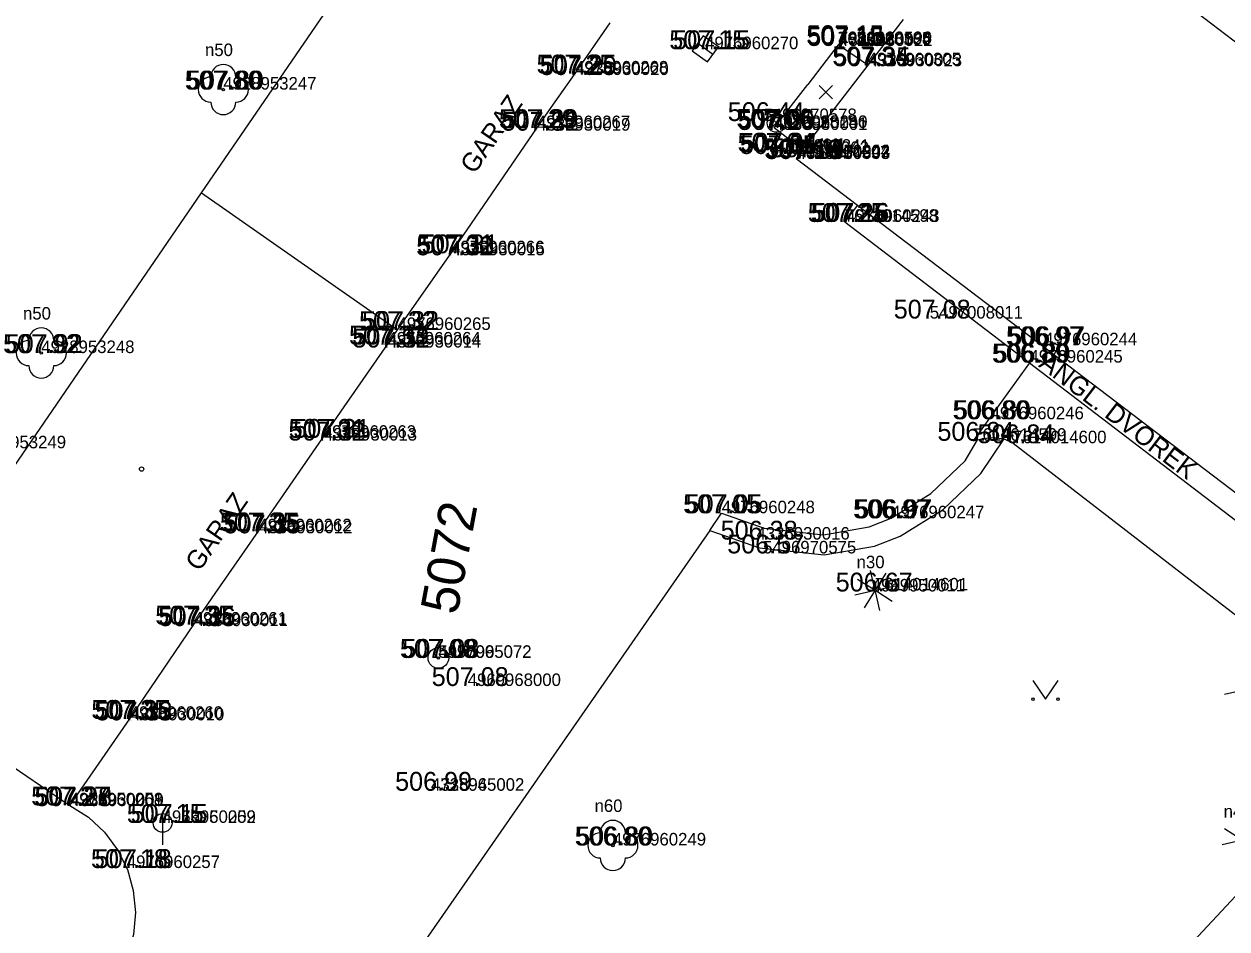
# Model space of a CAD drawing. Extents: x -669251 to -668549, y -1128351 to -1127698.
# Drawn here: x -668695.76 to -668647.77, y -1128038.19 to -1128002.1 of the extents above; entities that cross this region are included whole.
import ezdxf

# ---------------------------------------------------------------- set-up
doc = ezdxf.new("R2010")
doc.units = 0
for name, color, linetype in [('Vrstva 1', 7, 'Continuous'), ('Vrstva 10', 7, 'Continuous'), ('Vrstva 11', 7, 'Continuous'), ('Vrstva 2', 7, 'Continuous'), ('Vrstva 22', 7, 'Continuous'), ('Vrstva 27', 7, 'Continuous'), ('Vrstva 3', 7, 'Continuous'), ('Vrstva 33', 7, 'Continuous'), ('Vrstva 36', 7, 'Continuous'), ('Vrstva 41', 7, 'Continuous'), ('Vrstva 42', 7, 'Continuous'), ('Vrstva 47', 7, 'Continuous'), ('Vrstva 5', 7, 'Continuous'), ('Vrstva 58', 7, 'Continuous'), ('Vrstva 6', 7, 'Continuous'), ('Vrstva 63', 7, 'Continuous')]:
    doc.layers.add(name, color=color, linetype=linetype)

msp = doc.modelspace()

# ---------------------------------------------------------------- linework, layer by layer
at = {"layer": 'Vrstva 1'}
for p, q in [((-668663.29, -1128002.92), (-668663.29, -1128002.92)), ((-668663.29, -1128002.92), (-668663.29, -1128002.92)), ((-668663.28, -1128002.92), (-668663.28, -1128002.92)), ((-668663.259, -1128002.896), (-668663.259, -1128002.896)), ((-668663.24, -1128002.97), (-668663.24, -1128002.97)), ((-668668.59, -1128003.1), (-668668.59, -1128003.1)), ((-668662.1, -1128003.74), (-668662.1, -1128003.74)), ((-668662.06, -1128003.78), (-668662.06, -1128003.78)), ((-668673.78, -1128004.07), (-668673.78, -1128004.07)), ((-668673.76, -1128004.13), (-668673.76, -1128004.13)), ((-668687.81, -1128004.71), (-668687.81, -1128004.71)), ((-668675.3, -1128006.25), (-668675.3, -1128006.25)), ((-668675.29, -1128006.35), (-668675.29, -1128006.35)), ((-668666.258, -1128005.966), (-668666.258, -1128005.966)), ((-668665.85, -1128006.24), (-668665.85, -1128006.24)), ((-668665.85, -1128006.24), (-668665.85, -1128006.24)), ((-668665.83, -1128006.24), (-668665.83, -1128006.24)), ((-668665.83, -1128006.32), (-668665.83, -1128006.32)), ((-668665.77, -1128007.28), (-668665.77, -1128007.28)), ((-668665.74, -1128007.19), (-668665.74, -1128007.19)), ((-668664.954, -1128007.464), (-668664.954, -1128007.464)), ((-668664.93, -1128007.41), (-668664.93, -1128007.41)), ((-668664.93, -1128007.41), (-668664.93, -1128007.41)), ((-668664.93, -1128007.48), (-668664.93, -1128007.48)), ((-668663.016, -1128009.985), (-668663.016, -1128009.985)), ((-668662.96, -1128009.99), (-668662.96, -1128009.99)), ((-668678.72, -1128011.24), (-668678.72, -1128011.24)), ((-668678.7, -1128011.32), (-668678.7, -1128011.32)), ((-668659.629, -1128013.844), (-668659.629, -1128013.844)), ((-668680.86, -1128014.3), (-668680.86, -1128014.3)), ((-668681.26, -1128014.88), (-668681.26, -1128014.88)), ((-668681.24, -1128015), (-668681.24, -1128015)), ((-668655.07, -1128014.91), (-668655.07, -1128014.91)), ((-668695.07, -1128015.22), (-668695.07, -1128015.22)), ((-668655.65, -1128015.6), (-668655.65, -1128015.6)), ((-668657.2, -1128017.86), (-668657.2, -1128017.86)), ((-668683.84, -1128018.6), (-668683.84, -1128018.6)), ((-668683.8, -1128018.71), (-668683.8, -1128018.71)), ((-668657.894, -1128018.719), (-668657.894, -1128018.719)), ((-668656.296, -1128018.817), (-668656.296, -1128018.817)), ((-668667.93, -1128021.61), (-668667.93, -1128021.61)), ((-668661.17, -1128021.81), (-668661.17, -1128021.81)), ((-668686.41, -1128022.33), (-668686.41, -1128022.33)), ((-668686.38, -1128022.41), (-668686.38, -1128022.41)), ((-668666.54, -1128022.66), (-668666.54, -1128022.66)), ((-668666.279, -1128023.212), (-668666.279, -1128023.212)), ((-668661.94, -1128024.73), (-668661.94, -1128024.73)), ((-668661.817, -1128024.689), (-668661.817, -1128024.689)), ((-668688.99, -1128026.05), (-668688.99, -1128026.05)), ((-668688.95, -1128026.11), (-668688.95, -1128026.11)), ((-668679.232, -1128027.376), (-668679.232, -1128027.376)), ((-668679.23, -1128027.38), (-668679.23, -1128027.38)), ((-668679.23, -1128027.38), (-668679.23, -1128027.38)), ((-668678.06, -1128028.5), (-668678.06, -1128028.5)), ((-668691.54, -1128029.81), (-668691.54, -1128029.81)), ((-668691.49, -1128029.87), (-668691.49, -1128029.87)), ((-668679.521, -1128032.677), (-668679.521, -1128032.677)), ((-668679.52, -1128032.68), (-668679.52, -1128032.68)), ((-668693.93, -1128033.26), (-668693.93, -1128033.26)), ((-668693.93, -1128033.26), (-668693.93, -1128033.26)), ((-668693.9, -1128033.29), (-668693.9, -1128033.29)), ((-668690.23, -1128033.96), (-668690.23, -1128033.96)), ((-668690.23, -1128033.96), (-668690.23, -1128033.96)), ((-668672.27, -1128034.86), (-668672.27, -1128034.86)), ((-668691.66, -1128035.76), (-668691.66, -1128035.76))]:
    msp.add_line(p, q, dxfattribs=at)
at = {"layer": 'Vrstva 10'}
for p, q in [((-668655.655, -1128015.606), (-668657.894, -1128018.719)), ((-668658.216, -1128019.518), (-668657.726, -1128018.677)), ((-668657.587, -1128020.023), (-668656.658, -1128018.643)), ((-668659.582, -1128020.827), (-668658.216, -1128019.518)), ((-668659.088, -1128021.462), (-668657.587, -1128020.023)), ((-668661.17, -1128021.81), (-668659.582, -1128020.827)), ((-668668.403, -1128022.291), (-668667.93, -1128021.61)), ((-668667.93, -1128021.61), (-668666.24, -1128022.207)), ((-668660.808, -1128022.527), (-668659.088, -1128021.462)), ((-668666.24, -1128022.207), (-668663.87, -1128022.465)), ((-668663.87, -1128022.465), (-668662.041, -1128022.15)), ((-668662.041, -1128022.15), (-668661.17, -1128021.81)), ((-668668.403, -1128022.291), (-668686.448, -1128048.279)), ((-668668.403, -1128022.291), (-668666.419, -1128022.991)), ((-668661.83, -1128022.925), (-668660.808, -1128022.527)), ((-668666.419, -1128022.991), (-668663.84, -1128023.272)), ((-668663.84, -1128023.272), (-668661.83, -1128022.925))]:
    msp.add_line(p, q, dxfattribs=at)
for points in [[(-668657.894, -1128018.719), (-668657.726, -1128018.677)], [(-668657.726, -1128018.677), (-668657.36, -1128018.609), (-668657.074, -1128018.591), (-668656.658, -1128018.643)], [(-668656.658, -1128018.643), (-668656.296, -1128018.817), (-668648.83, -1128024.582), (-668641.364, -1128030.347)], [(-668693.93, -1128033.26), (-668693.19, -1128033.731), (-668692.548, -1128034.328), (-668692.024, -1128035.031), (-668691.637, -1128035.818), (-668691.399, -1128036.662), (-668691.318, -1128037.535), (-668691.397, -1128038.409), (-668691.632, -1128039.253), (-668691.78, -1128039.6)]]:
    msp.add_lwpolyline(points, dxfattribs=at)
at = {"layer": 'Vrstva 11'}
for p, q in [((-668662.511, -1128009.321), (-668663.016, -1128009.985)), ((-668663.016, -1128009.985), (-668655.655, -1128015.606)), ((-668655.655, -1128015.606), (-668641.204, -1128026.641))]:
    msp.add_line(p, q, dxfattribs=at)
at = {"layer": 'Vrstva 22'}
for p, q in [((-668661.825, -1128024.649), (-668661.997, -1128023.895)), ((-668661.383, -1128023.999), (-668661.797, -1128024.655)), ((-668661.851, -1128024.669), (-668662.507, -1128024.255)), ((-668661.777, -1128024.681), (-668661.023, -1128024.509)), ((-668662.611, -1128024.869), (-668661.857, -1128024.697)), ((-668661.837, -1128024.723), (-668662.251, -1128025.379)), ((-668661.809, -1128024.729), (-668661.637, -1128025.483)), ((-668661.127, -1128025.123), (-668661.783, -1128024.709)), ((-668647.869, -1128028.828), (-668647.115, -1128028.656)), ((-668647.21, -1128034.616), (-668647.866, -1128034.202)), ((-668647.97, -1128034.816), (-668647.216, -1128034.644))]:
    msp.add_line(p, q, dxfattribs=at)
for centre, radius in [((-668687.81, -1128004.71), 0.05), ((-668695.07, -1128015.22), 0.05), ((-668661.817, -1128024.689), 0.04), ((-668672.27, -1128034.86), 0.05)]:
    msp.add_circle(centre, radius, dxfattribs=at)
for centre, start, end in [((-668687.81, -1128004.21), 0, 180), ((-668688.31, -1128004.71), 90, 270), ((-668687.31, -1128004.71), 270, 90), ((-668687.81, -1128005.21), 180, 0), ((-668695.07, -1128014.72), 0, 180), ((-668695.57, -1128015.22), 90, 270), ((-668694.57, -1128015.22), 270, 90), ((-668695.07, -1128015.72), 180, 0), ((-668672.27, -1128034.36), 0, 180), ((-668672.77, -1128034.86), 90, 270), ((-668671.77, -1128034.86), 270, 90), ((-668672.27, -1128035.36), 180, 0)]:
    msp.add_arc(centre, 0.5, start, end, dxfattribs=at)
at = {"layer": 'Vrstva 27'}
for p, q in [((-668668.884, -1128002.866), (-668668.277, -1128003.305)), ((-668690.23, -1128033.585), (-668690.23, -1128034.835))]:
    msp.add_line(p, q, dxfattribs=at)
msp.add_lwpolyline([(-668669.104, -1128003.168), (-668668.496, -1128003.608), (-668668.056, -1128003.001), (-668668.664, -1128002.561)], close=True, dxfattribs=at)
msp.add_circle((-668690.23, -1128033.96), 0.375, dxfattribs=at)
at = {"layer": 'Vrstva 33'}
for p, q in [((-668666.005, -1128005.775), (-668665.475, -1128006.305)), ((-668666.005, -1128006.305), (-668665.475, -1128005.775)), ((-668665.74, -1128007.19), (-668665.74, -1128006.415))]:
    msp.add_line(p, q, dxfattribs=at)
for centre, radius in [((-668665.74, -1128006.04), 0.375), ((-668665.74, -1128007.19), 0.19), ((-668665.74, -1128007.19), 0.05)]:
    msp.add_circle(centre, radius, dxfattribs=at)
at = {"layer": 'Vrstva 36'}
for p, q in [((-668655.512, -1128028.277), (-668655.012, -1128029.027)), ((-668655.012, -1128029.027), (-668654.512, -1128028.277))]:
    msp.add_line(p, q, dxfattribs=at)
for centre in [(-668655.513, -1128029.027), (-668654.513, -1128029.027)]:
    msp.add_circle(centre, 0.05, dxfattribs=at)
at = {"layer": 'Vrstva 5'}
for p, q in [((-668688.674, -1128008.827), (-668680.57, -1127997.01)), ((-668631.975, -1128014.617), (-668653.726, -1127998.018)), ((-668660.694, -1128001.913), (-668662.1, -1128003.74)), ((-668663.28, -1128002.92), (-668663.767, -1128003.554)), ((-668662.1, -1128003.74), (-668663.28, -1128002.92)), ((-668662.1, -1128003.74), (-668664.7, -1128007.112)), ((-668674.728, -1128005.429), (-668673.78, -1128004.07)), ((-668665.83, -1128006.24), (-668664.498, -1128004.506)), ((-668678.72, -1128011.24), (-668675.3, -1128006.25)), ((-668664.7, -1128007.112), (-668665.83, -1128006.24)), ((-668664.7, -1128007.112), (-668664.954, -1128007.464)), ((-668664.954, -1128007.464), (-668662.511, -1128009.321)), ((-668700.28, -1128025.75), (-668688.674, -1128008.827)), ((-668688.674, -1128008.827), (-668680.86, -1128014.3)), ((-668662.511, -1128009.321), (-668640.662, -1128025.932)), ((-668680.86, -1128014.3), (-668680.458, -1128013.726)), ((-668681.26, -1128014.88), (-668680.86, -1128014.3)), ((-668683.84, -1128018.6), (-668682.985, -1128017.367)), ((-668686.41, -1128022.33), (-668685.558, -1128021.094)), ((-668688.99, -1128026.05), (-668688.135, -1128024.817)), ((-668701.766, -1128027.939), (-668693.93, -1128033.26)), ((-668691.54, -1128029.81), (-668690.698, -1128028.568)), ((-668652.247, -1128042.052), (-668641.364, -1128030.347)), ((-668693.93, -1128033.26), (-668693.246, -1128032.273))]:
    msp.add_line(p, q, dxfattribs=at)
at = {"layer": 'Vrstva 58'}
for p, q in [((-668663.511, -1128005.074), (-668664.042, -1128004.544)), ((-668664.042, -1128005.074), (-668663.511, -1128004.544))]:
    msp.add_line(p, q, dxfattribs=at)
msp.add_circle((-668691.067, -1128019.847), 0.0875, dxfattribs=at)
at = {"layer": 'Vrstva 6'}
for p, q in [((-668673.78, -1128004.07), (-668672.38, -1128002.05)), ((-668663.767, -1128003.554), (-668664.498, -1128004.506)), ((-668675.3, -1128006.25), (-668674.728, -1128005.429)), ((-668680.458, -1128013.726), (-668678.72, -1128011.24)), ((-668682.985, -1128017.367), (-668681.26, -1128014.88)), ((-668685.558, -1128021.094), (-668683.84, -1128018.6)), ((-668688.135, -1128024.817), (-668686.41, -1128022.33)), ((-668690.698, -1128028.568), (-668688.99, -1128026.05)), ((-668693.246, -1128032.273), (-668691.54, -1128029.81))]:
    msp.add_line(p, q, dxfattribs=at)
at = {"layer": 'Vrstva 63'}
for radius in [0.412, 0.412, 0.05, 0.05]:
    msp.add_circle((-668679.23, -1128027.38), radius, dxfattribs=at)

# ---------------------------------------------------------------- texts
at = {"layer": 'Vrstva 2'}
for s, p in [('4976960304', (-668663.28, -1128002.92)), ('7682018185', (-668663.29, -1128002.92)), ('7682028185', (-668663.29, -1128002.92)), ('7960020596', (-668663.259, -1128002.896)), ('4335930022', (-668663.24, -1128002.97)), ('4976960270', (-668668.59, -1128003.1)), ('4976960305', (-668662.1, -1128003.74)), ('4335930023', (-668662.06, -1128003.78)), ('4976960268', (-668673.78, -1128004.07)), ('4335930020', (-668673.76, -1128004.13)), ('4928953247', (-668687.81, -1128004.71)), ('4976960267', (-668675.3, -1128006.25)), ('4335930019', (-668675.29, -1128006.35)), ('5496970578', (-668666.258, -1128005.966)), ('7682018186', (-668665.85, -1128006.24)), ('7682028186', (-668665.85, -1128006.24)), ('4976960240', (-668665.83, -1128006.24)), ('4335930001', (-668665.83, -1128006.32)), ('4335930002', (-668665.77, -1128007.28)), ('4976960241', (-668665.74, -1128007.19)), ('7614014597', (-668664.954, -1128007.464)), ('4969950004', (-668664.93, -1128007.41)), ('4976960242', (-668664.93, -1128007.41)), ('4335930003', (-668664.93, -1128007.48)), ('7614014598', (-668663.016, -1128009.985)), ('4976960243', (-668662.96, -1128009.99)), ('4976960266', (-668678.72, -1128011.24)), ('4335930015', (-668678.7, -1128011.32)), ('5497008011', (-668659.629, -1128013.844)), ('4976960265', (-668680.86, -1128014.3)), ('4976960264', (-668681.26, -1128014.88)), ('4335930014', (-668681.24, -1128015)), ('4976960244', (-668655.07, -1128014.91)), ('4928953248', (-668695.07, -1128015.22)), ('4976960245', (-668655.65, -1128015.6)), ('4976960246', (-668657.2, -1128017.86)), ('4976960263', (-668683.84, -1128018.6)), ('4335930013', (-668683.8, -1128018.71)), ('7614014599', (-668657.894, -1128018.719)), ('7614014600', (-668656.296, -1128018.817)), ('4928953249', (-668697.8, -1128019.02)), ('4976960248', (-668667.93, -1128021.61)), ('4976960247', (-668661.17, -1128021.81)), ('4976960262', (-668686.41, -1128022.33)), ('4335930012', (-668686.38, -1128022.41)), ('4335930016', (-668666.54, -1128022.66)), ('5496970575', (-668666.279, -1128023.212)), ('4969950011', (-668661.94, -1128024.73)), ('7614014601', (-668661.817, -1128024.689)), ('4976960261', (-668688.99, -1128026.05)), ('4335930011', (-668688.95, -1128026.11)), ('4976965072', (-668679.23, -1128027.38)), ('4977005072', (-668679.23, -1128027.38)), ('5496995072', (-668679.232, -1128027.376)), ('4969968000', (-668678.06, -1128028.5)), ('4976960260', (-668691.54, -1128029.81)), ('4335930010', (-668691.49, -1128029.87)), ('4728965002', (-668679.521, -1128032.677)), ('4335945002', (-668679.52, -1128032.68)), ('4969950001', (-668693.93, -1128033.26)), ('4976960258', (-668693.93, -1128033.26)), ('4335930009', (-668693.9, -1128033.29)), ('4969950002', (-668690.23, -1128033.96)), ('4976960259', (-668690.23, -1128033.96)), ('4976960249', (-668672.27, -1128034.86)), ('4976960257', (-668691.66, -1128035.76))]:
    msp.add_text(s, height=0.5, dxfattribs=at).set_placement(p)
at = {"layer": 'Vrstva 3'}
for s, p in [('507.15 ', (-668670.019, -1128003.1)), ('507.15 ', (-668669.864, -1128003.1)), ('507.13 ', (-668664.554, -1128002.92)), ('507.15 ', (-668664.533, -1128002.896)), ('507.15 ', (-668664.514, -1128002.97)), ('507.34 ', (-668663.515, -1128003.74)), ('507.35 ', (-668663.475, -1128003.78)), ('507.25 ', (-668675.315, -1128004.07)), ('507.25 ', (-668675.195, -1128004.07)), ('507.29 ', (-668675.178, -1128004.13)), ('507.80 ', (-668689.345, -1128004.71)), ('507.80 ', (-668689.261, -1128004.71)), ('506.44 ', (-668667.687, -1128005.966)), ('507.29 ', (-668676.816, -1128006.25)), ('507.29 ', (-668676.718, -1128006.25)), ('507.32 ', (-668676.705, -1128006.35)), ('507.06 ', (-668667.346, -1128006.24)), ('507.06 ', (-668667.29, -1128006.24)), ('507.20 ', (-668667.281, -1128006.32)), ('507.04 ', (-668667.294, -1128007.19)), ('507.05 ', (-668667.206, -1128007.28)), ('507.04 ', (-668667.176, -1128007.19)), ('507.19 ', (-668666.23, -1128007.464)), ('507.18 ', (-668666.204, -1128007.48)), ('507.11 ', (-668666.182, -1128007.41)), ('507.11 ', (-668665.967, -1128007.41)), ('507.25 ', (-668664.495, -1128009.99)), ('507.25 ', (-668664.375, -1128009.99)), ('507.16 ', (-668664.312, -1128009.985)), ('507.32 ', (-668680.115, -1128011.32)), ('507.31 ', (-668680.078, -1128011.24)), ('507.31 ', (-668679.898, -1128011.24)), ('507.08 ', (-668661.065, -1128013.844)), ('507.32 ', (-668682.395, -1128014.3)), ('507.32 ', (-668682.275, -1128014.3)), ('507.92 ', (-668696.594, -1128015.22)), ('507.92 ', (-668696.487, -1128015.22)), ('507.33 ', (-668682.795, -1128014.88)), ('507.33 ', (-668682.675, -1128014.88)), ('507.32 ', (-668682.655, -1128015)), ('506.97 ', (-668656.586, -1128014.91)), ('506.97 ', (-668656.501, -1128014.91)), ('506.89 ', (-668657.15, -1128015.6)), ('506.89 ', (-668657.082, -1128015.6)), ('506.80 ', (-668658.72, -1128017.86)), ('506.80 ', (-668658.664, -1128017.86)), ('507.31 ', (-668685.198, -1128018.6)), ('507.31 ', (-668685.018, -1128018.6)), ('507.32 ', (-668685.215, -1128018.71)), ('506.84 ', (-668659.323, -1128018.719)), ('506.84 ', (-668657.725, -1128018.817)), ('507.05 ', (-668669.465, -1128021.61)), ('507.05 ', (-668669.366, -1128021.61)), ('506.97 ', (-668662.686, -1128021.81)), ('506.97 ', (-668662.601, -1128021.81)), ('507.35 ', (-668687.945, -1128022.33)), ('507.35 ', (-668687.825, -1128022.33)), ('507.35 ', (-668687.795, -1128022.41)), ('506.38 ', (-668667.969, -1128022.66)), ('506.57 ', (-668667.708, -1128023.212)), ('506.67 ', (-668663.382, -1128024.73)), ('507.35 ', (-668690.525, -1128026.05)), ('507.35 ', (-668690.405, -1128026.05)), ('507.36 ', (-668690.388, -1128026.11)), ('507.08 ', (-668680.765, -1128027.38)), ('507.08 ', (-668680.668, -1128027.376)), ('507.08 ', (-668680.666, -1128027.38)), ('507.08 ', (-668680.666, -1128027.38)), ('507.08 ', (-668679.496, -1128028.5)), ('507.35 ', (-668693.075, -1128029.81)), ('507.35 ', (-668692.955, -1128029.81)), ('507.33 ', (-668692.905, -1128029.87)), ('506.99 ', (-668680.955, -1128032.677)), ('506.99 ', (-668680.954, -1128032.68)), ('507.27 ', (-668695.473, -1128033.26)), ('507.27 ', (-668695.345, -1128033.26)), ('507.28 ', (-668695.315, -1128033.29)), ('507.15 ', (-668691.659, -1128033.96)), ('507.15 ', (-668691.504, -1128033.96)), ('506.80 ', (-668673.79, -1128034.86)), ('506.80 ', (-668673.734, -1128034.86)), ('507.18 ', (-668693.089, -1128035.76)), ('507.18 ', (-668692.934, -1128035.76))]:
    msp.add_text(s, height=0.75, dxfattribs=at).set_placement(p)
at = {"layer": 'Vrstva 41'}
for rotation, p in [(55.5744, (-668677.792, -1128008.118)), (55.2546, (-668688.764, -1128023.969))]:
    msp.add_text('GARAZ', height=0.75, rotation=rotation, dxfattribs=at).set_placement(p)
at = {"layer": 'Vrstva 42'}
msp.add_text('ANGL. DVOREK', height=0.75, rotation=322.6341, dxfattribs=at).set_placement((-668655.319, -1128015.739))
at = {"layer": 'Vrstva 47'}
for s, height, p in [('n50', 0.499, (-668688.539, -1128003.374)), ('n50', 0.499, (-668695.799, -1128013.884)), ('n30', 0.5, (-668662.547, -1128023.803)), ('n60', 0.499, (-668672.999, -1128033.524)), ('n40', 0.5, (-668647.906, -1128033.75))]:
    msp.add_text(s, height=height, dxfattribs=at).set_placement(p)
at = {"layer": 'Vrstva 63'}
msp.add_text('5072', height=1.5, rotation=79.5014, dxfattribs=at).set_placement((-668678.479, -1128025.7))
msp.add_text('5072', height=1.5, rotation=79.5014, dxfattribs=at).set_placement((-668678.479, -1128025.7))
msp.add_text('5072', height=1.5, rotation=79.5014, dxfattribs=at).set_placement((-668678.479, -1128025.7))
msp.add_text('5072', height=1.5, rotation=79.5014, dxfattribs=at).set_placement((-668678.479, -1128025.7))

doc.saveas('drawing.dxf')
